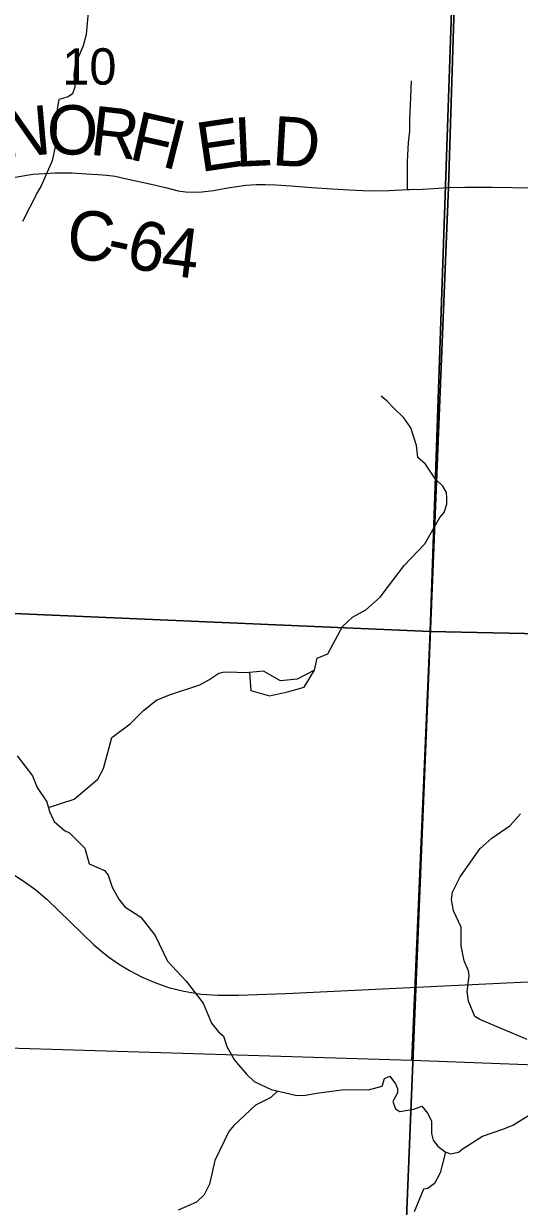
# Model space of a CAD drawing. Extents: x 0 to 34, y 0 to 22.
# Drawn here: x 5.115 to 5.686, y 17.641 to 19.003 of the extents above; entities that cross this region are included whole.
import ezdxf

# ---------------------------------------------------------------- set-up
doc = ezdxf.new("R2010")
doc.units = 0
for name, color, linetype in [('GM_X_County_Road', 7, 'Continuous'), ('GM_X_County_Road_Text', 7, 'Continuous'), ('GM_X_Minor_Lake', 7, 'Continuous'), ('GM_X_Minor_River', 7, 'Continuous'), ('GM_X_Rail_Line', 7, 'Continuous'), ('GM_X_Section', 7, 'Continuous'), ('GM_X_Section_Text', 7, 'Continuous'), ('GM_X_Township_Road', 7, 'Continuous')]:
    doc.layers.add(name, color=color, linetype=linetype)

msp = doc.modelspace()

# ---------------------------------------------------------------- linework, layer by layer
at = {"layer": 'GM_X_County_Road'}
for points in [[(5.1057, 18.8263), (5.126, 18.8297), (5.1391, 18.8305), (5.1517, 18.8311), (5.1712, 18.8311), (5.1878, 18.8303), (5.2012, 18.8295), (5.2113, 18.8287), (5.2208, 18.8273), (5.2322, 18.8249), (5.2622, 18.8182), (5.2788, 18.8143), (5.2932, 18.8107), (5.3017, 18.8093), (5.3112, 18.809), (5.3206, 18.8095), (5.3339, 18.8111), (5.3504, 18.8141), (5.3714, 18.817), (5.3836, 18.8178), (5.3935, 18.818), (5.4055, 18.8176), (5.4233, 18.8163), (5.4469, 18.8145), (5.471, 18.8127), (5.4902, 18.8117), (5.5134, 18.8107), (5.5363, 18.8111), (5.5575, 18.8121)], [(5.5575, 18.8121), (5.5598, 18.8121), (5.5746, 18.8125), (5.5873, 18.8133), (5.604, 18.8143)], [(5.604, 18.8143), (5.6049, 18.8143), (5.6235, 18.8148), (5.6359, 18.8147), (5.6547, 18.8147), (5.6782, 18.8145), (5.7153, 18.8135), (5.7611, 18.8129), (5.7927, 18.8123), (5.8306, 18.8111), (5.8691, 18.8101), (5.9006, 18.8092), (5.9419, 18.8076), (5.976, 18.8064), (6.0025, 18.8042), (6.027, 18.802), (6.0548, 18.7997), (6.0677, 18.7988)]]:
    msp.add_lwpolyline(points, dxfattribs=at)
at = {"layer": 'GM_X_Minor_Lake'}
for points in [[(5.3753, 18.2559), (5.3771, 18.235), (5.3983, 18.2289), (5.4191, 18.2335), (5.4384, 18.2388), (5.4502, 18.2585), (5.4305, 18.2479), (5.4112, 18.246), (5.3915, 18.2574)], [(5.3753, 18.2559), (5.3771, 18.235), (5.3983, 18.2289), (5.4191, 18.2335), (5.4384, 18.2388), (5.4502, 18.2585), (5.4305, 18.2479), (5.4112, 18.246), (5.3915, 18.2574), (5.3753, 18.2559)], [(5.3915, 18.2574), (5.3753, 18.2559)]]:
    msp.add_lwpolyline(points, dxfattribs=at)
at = {"layer": 'GM_X_Minor_River'}
for points in [[(5.1899, 19.0211), (5.1874, 18.9908), (5.1841, 18.9774), (5.1747, 18.9561), (5.1733, 18.9447), (5.1745, 18.9299), (5.1715, 18.9223), (5.1666, 18.9189), (5.156, 18.9158), (5.1527, 18.8976), (5.1525, 18.8649), (5.1484, 18.8452), (5.1357, 18.8162), (5.1312, 18.809), (5.114, 18.7751)], [(5.4502, 18.2585), (5.4535, 18.2721), (5.4656, 18.2771), (5.4825, 18.3087), (5.4941, 18.3194), (5.5092, 18.3278), (5.5258, 18.3424), (5.5536, 18.3789), (5.5773, 18.4041), (5.5946, 18.4342), (5.5995, 18.4399), (5.6028, 18.4498), (5.6028, 18.457), (5.6024, 18.4631), (5.5982, 18.4703), (5.5894, 18.4786), (5.578, 18.4956), (5.5693, 18.5035), (5.5677, 18.5172), (5.5612, 18.5377), (5.5532, 18.549), (5.5414, 18.5607), (5.5338, 18.5683), (5.5269, 18.5739)], [(5.1439, 18.1001), (5.1736, 18.11), (5.2008, 18.133), (5.2075, 18.1451), (5.2149, 18.1737), (5.2168, 18.1809), (5.2379, 18.1966), (5.2533, 18.2118), (5.2684, 18.2237), (5.2835, 18.2302), (5.3182, 18.2414), (5.3288, 18.2472), (5.3401, 18.2548), (5.3462, 18.2567), (5.3753, 18.2559)], [(5.1079, 18.1598), (5.1258, 18.1367), (5.1308, 18.1231), (5.1423, 18.1068), (5.145, 18.0958), (5.1507, 18.0841), (5.1625, 18.0739), (5.1682, 18.0709), (5.186, 18.0535), (5.191, 18.0354), (5.2085, 18.0275), (5.2127, 18.0222), (5.2173, 18.0085), (5.2249, 17.9945), (5.2318, 17.9858), (5.2503, 17.9738), (5.2667, 17.953), (5.2809, 17.9231), (5.3025, 17.9004), (5.322, 17.8747), (5.3315, 17.852), (5.3399, 17.8418), (5.3456, 17.8369), (5.3494, 17.8248), (5.3582, 17.8093), (5.3723, 17.7926), (5.381, 17.7847), (5.4004, 17.7753), (5.4284, 17.769), (5.4379, 17.7687), (5.4526, 17.7711), (5.4844, 17.7754), (5.5124, 17.7752), (5.5282, 17.7791), (5.5308, 17.7882), (5.5369, 17.7909), (5.5437, 17.7818), (5.546, 17.7765), (5.5457, 17.7716), (5.5404, 17.7617), (5.5435, 17.7533), (5.5484, 17.7499), (5.5647, 17.7527), (5.5737, 17.7562), (5.5806, 17.7478), (5.5848, 17.7391), (5.5849, 17.7247), (5.5868, 17.7171), (5.5921, 17.7103), (5.6008, 17.7035), (5.6069, 17.7013), (5.616, 17.7032), (5.6216, 17.7074), (5.6435, 17.7216), (5.6684, 17.7301), (5.6786, 17.7343), (5.7103, 17.7539)], [(5.6952, 17.8331), (5.6406, 17.856), (5.6349, 17.8597), (5.6276, 17.8772), (5.626, 17.8882), (5.6282, 17.9064), (5.6274, 17.9121), (5.6225, 17.9238), (5.619, 17.9409), (5.6192, 17.9625), (5.6104, 17.9811), (5.6081, 17.9943), (5.6092, 18.0027), (5.6178, 18.0202), (5.6411, 18.053), (5.6543, 18.0648), (5.6754, 18.0797), (5.6874, 18.0931)], [(5.4076, 17.7737), (5.4, 17.7662), (5.3823, 17.7574), (5.3575, 17.7341), (5.3518, 17.7269), (5.3357, 17.6937), (5.3294, 17.6664), (5.3231, 17.6542), (5.3144, 17.6458), (5.2933, 17.6366)], [(5.6012, 17.7034), (5.5949, 17.6796), (5.5885, 17.667), (5.5806, 17.6613), (5.5757, 17.6605), (5.5649, 17.6346)]]:
    msp.add_lwpolyline(points, dxfattribs=at)
at = {"layer": 'GM_X_Rail_Line'}
for points in [[(6.4497, 20.3378), (5.6557, 20.3708), (5.6553, 20.3577), (5.6546, 20.3418), (5.654, 20.3257), (5.6534, 20.3099), (5.6525, 20.282), (5.6508, 20.2455), (5.6504, 20.2297), (5.6498, 20.2109), (5.648, 20.1614), (5.6476, 20.1497), (5.6463, 20.1174), (5.6454, 20.0833), (5.644, 20.0435), (5.6417, 19.9935), (5.6412, 19.9842), (5.6047, 18.8149), (5.5414, 17.2599)], [(5.5414, 17.2599), (5.6047, 18.8149), (5.6412, 19.9842), (5.6417, 19.9935)], [(5.1038, 18.0231), (5.1162, 18.0152), (5.1293, 18.0054), (5.1424, 17.9942), (5.1964, 17.9419), (5.2033, 17.9363), (5.2132, 17.9283), (5.2246, 17.9203), (5.2374, 17.9124), (5.2517, 17.9049), (5.2665, 17.8987), (5.2823, 17.893), (5.2997, 17.8888), (5.3198, 17.8854), (5.3391, 17.884), (5.3628, 17.8841), (5.4172, 17.8862), (5.6713, 17.8983), (5.7208, 17.9005)]]:
    msp.add_lwpolyline(points, dxfattribs=at)
at = {"layer": 'GM_X_Section'}
for points in [[(5.6189, 19.331), (5.5833, 18.3028), (4.58, 18.3465), (4.6214, 19.3661)], [(6.5918, 19.2905), (6.5595, 18.2824), (5.5833, 18.3028), (5.6189, 19.331)], [(5.5833, 18.3028), (5.5625, 17.8089), (4.5566, 17.8394), (4.58, 18.3465)], [(6.5595, 18.2824), (6.5395, 17.7719), (5.5625, 17.8089), (5.5833, 18.3028)]]:
    msp.add_lwpolyline(points, close=True, dxfattribs=at)
at = {"layer": 'GM_X_Township_Road'}
msp.add_lwpolyline([(5.5575, 18.8121), (5.5572, 18.8249), (5.5574, 18.8444), (5.5585, 18.8661), (5.5599, 18.8791), (5.5601, 18.8928), (5.5613, 18.9183), (5.5618, 18.9373)], dxfattribs=at)

# ---------------------------------------------------------------- texts
at = {"layer": 'GM_X_County_Road_Text'}
for s, rotation, p in [('N', 4.9092, (5.0936, 18.8484)), ('O', 359.592, (5.142, 18.8526)), ('R', 353.5702, (5.1904, 18.8524)), ('F', 347.2949, (5.2352, 18.8474)), ('E', 8.3729, (5.3191, 18.8321)), ('L', 2.7096, (5.3597, 18.8381)), ('D', 356.5446, (5.4005, 18.8402)), ('I', 345.7725, (5.2722, 18.8391)), ('C', 355.6166, (5.1639, 18.7325)), ('6', 345.9284, (5.2307, 18.7244)), ('4', 352.9112, (5.2721, 18.7145)), ('-', 347.8251, (5.2084, 18.7292))]:
    msp.add_text(s, height=0.0568, rotation=rotation, dxfattribs=at).set_placement(p)
at = {"layer": 'GM_X_Section_Text'}
msp.add_text('10', height=0.04186, rotation=0, dxfattribs=at).set_placement((5.16, 18.9329))

doc.saveas('drawing.dxf')
